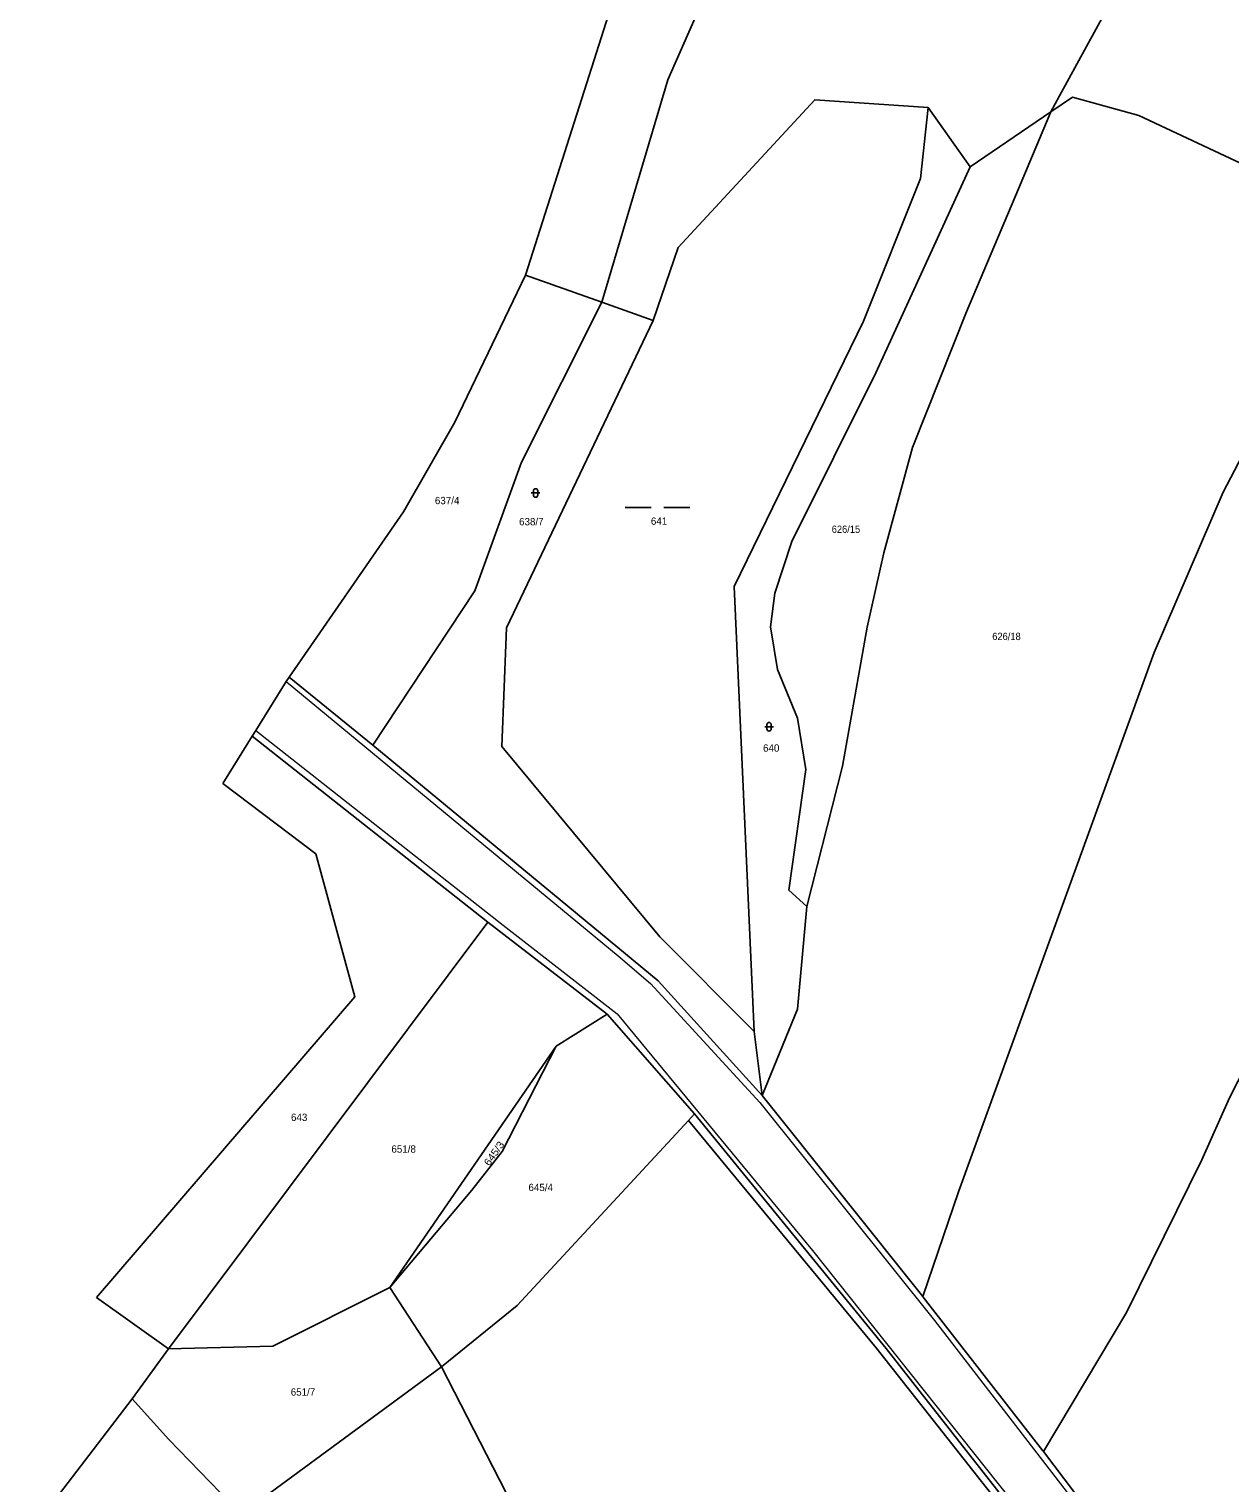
# Model space of a CAD drawing. Extents: x -687135 to -684370, y -1007309 to -1005782.
# Drawn here: x -685352.6 to -685073.8, y -1006317.9 to -1005980.6 of the extents above; entities that cross this region are included whole.
import ezdxf

# ---------------------------------------------------------------- set-up
doc = ezdxf.new("R2010")
doc.units = 0
doc.header["$LTSCALE"] = 0.68
for name, color, linetype, lineweight in [('1', 7, 'Continuous', 25), ('3', 7, 'Continuous', 25), ('4', 7, 'Continuous', 13)]:
    doc.layers.add(name, color=color, linetype=linetype, lineweight=lineweight)
doc.layers.add('2', color=7, linetype='Continuous')

msp = doc.modelspace()

# ---------------------------------------------------------------- linework, layer by layer
at = {"layer": '1'}
for p, q in [((-685218.37, -1006209.16), (-685230.23, -1006216.55)), ((-685230.23, -1006216.55), (-685268.8, -1006272.58)), ((-685198.1, -1006232.27), (-685199.53, -1006233.83)), ((-685268.8, -1006272.58), (-685256.82, -1006291)), ((-685256.82, -1006291), (-685303.33, -1006325.19))]:
    msp.add_line(p, q, dxfattribs=at)
for points in [[(-685201.33, -1005937.1), (-685215.2, -1005968.19), (-685237.31, -1006037.69)], [(-685186.26, -1005951.34), (-685204.26, -1005992.33), (-685219.65, -1006043.93), (-685207.69, -1006048.16)], [(-685115.38, -1005999.81), (-685113.34, -1005996.06), (-685094.6, -1005961.65)], [(-685207.69, -1006048.16), (-685201.93, -1006031.22), (-685170.17, -1005996.98), (-685143.84, -1005998.76)], [(-685043.78, -1006024.6), (-685094.94, -1006000.61), (-685110.34, -1005996.38), (-685115.38, -1005999.81)], [(-685143.84, -1005998.76), (-685145.67, -1006015.24), (-685158.9, -1006048.35), (-685188.9, -1006109.89), (-685184.28, -1006213.17), (-685182.43, -1006228.06)], [(-685172.02, -1006184.19), (-685163.73, -1006151.58), (-685158.05, -1006119.33), (-685154.12, -1006102.12), (-685147.52, -1006077.65), (-685134.94, -1006046.18), (-685122.85, -1006017.63), (-685115.38, -1005999.81)], [(-685143.84, -1005998.76), (-685134.13, -1006012.57), (-685115.38, -1005999.81)], [(-685172.02, -1006184.19), (-685176.18, -1006180.38), (-685172.25, -1006152.4), (-685174.22, -1006140.49), (-685178.84, -1006129.17), (-685180.47, -1006119.27), (-685179.43, -1006111.45), (-685175.49, -1006099.47), (-685156.01, -1006060.35), (-685134.13, -1006012.57)], [(-685145.13, -1006274.7), (-685136.85, -1006250.38), (-685091.37, -1006125.23), (-685075.37, -1006088.01), (-685067.37, -1006072.83), (-685050.82, -1006039.99), (-685046.05, -1006029.56), (-685043.78, -1006024.6)], [(-685272.75, -1006146.75), (-685249.08, -1006110.89), (-685238.29, -1006081.04), (-685219.65, -1006043.93), (-685237.31, -1006037.69), (-685253.78, -1006071.82)], [(-685207.69, -1006048.16), (-685241.72, -1006119.52), (-685242.87, -1006147.07), (-685206.16, -1006191.21), (-685184.28, -1006213.17)], [(-685117.08, -1006310.67), (-685097.85, -1006278.37), (-685080.32, -1006242.98), (-685073.88, -1006228.61), (-685048.94, -1006179.58), (-685036.71, -1006155.62), (-685020.67, -1006123.9), (-684995.04, -1006079.93), (-684987.31, -1006061.26), (-684983.8, -1006052.73)], [(-685253.78, -1006071.82), (-685265.69, -1006092.63), (-685292.24, -1006130.92)], [(-685292.24, -1006130.92), (-685292.91, -1006131.99), (-685299.95, -1006143.32), (-685300.78, -1006144.66)], [(-685182.43, -1006228.06), (-685206.53, -1006201.42), (-685229.32, -1006182.6), (-685272.75, -1006146.75), (-685292.24, -1006130.92)], [(-685336.92, -1006274.87), (-685320.22, -1006286.8), (-685246.05, -1006187.82), (-685300.78, -1006144.66), (-685307.57, -1006155.67)], [(-685307.57, -1006155.67), (-685286.01, -1006171.99), (-685276.95, -1006205.11), (-685293.09, -1006223.89), (-685336.92, -1006274.87)], [(-685182.43, -1006228.06), (-685174.22, -1006208), (-685172.02, -1006184.19)], [(-685246.05, -1006187.82), (-685218.37, -1006209.16), (-685198.1, -1006232.27)], [(-685268.8, -1006272.58), (-685249.83, -1006249.99), (-685242.79, -1006241.05), (-685230.23, -1006216.55)], [(-685117.08, -1006310.67), (-685117.2, -1006310.51), (-685145.04, -1006274.81), (-685145.13, -1006274.7), (-685182.43, -1006228.06)], [(-685256.82, -1006291), (-685239.28, -1006276.78), (-685199.53, -1006233.83)], [(-685199.53, -1006233.83), (-685155.92, -1006286.6), (-685117.05, -1006335.89), (-685095.12, -1006384.78), (-685075.56, -1006429.52)], [(-685061.94, -1006454.16), (-685073.28, -1006426.13), (-685089.64, -1006391.69), (-685115.59, -1006335.15), (-685153.62, -1006286.74), (-685198.1, -1006232.27)], [(-685268.8, -1006272.58), (-685296, -1006286.21), (-685320.22, -1006286.8), (-685321.45, -1006288.51), (-685328.64, -1006298.45)], [(-685175.13, -1006458.36), (-685198.89, -1006402.17), (-685211.49, -1006378.14), (-685237.4, -1006328.81), (-685256.82, -1006291)], [(-685303.33, -1006325.19), (-685320.13, -1006307.86), (-685328.64, -1006298.45), (-685352.59, -1006329.63)], [(-685091.4, -1006354.8), (-685102.68, -1006329.65), (-685117.08, -1006310.67)]]:
    msp.add_lwpolyline(points, dxfattribs=at)
at = {"layer": '3'}
for p, q in [((-685236.011, -1006088.221), (-685234.009, -1006088.221)), ((-685235.511, -1006087.721), (-685235.511, -1006088.722)), ((-685234.509, -1006088.722), (-685234.509, -1006087.721)), ((-685214.199, -1006091.6), (-685208.199, -1006091.6)), ((-685205.199, -1006091.6), (-685199.199, -1006091.6)), ((-685181.801, -1006142.451), (-685179.799, -1006142.451)), ((-685181.301, -1006141.951), (-685181.301, -1006142.952)), ((-685180.299, -1006142.952), (-685180.299, -1006141.951))]:
    msp.add_line(p, q, dxfattribs=at)
for centre, start, end in [((-685235.01, -1006087.7209), 0, 180), ((-685235.01, -1006088.7209), 180, 359.98789), ((-685180.8, -1006141.9509), 0, 180), ((-685180.8, -1006142.9509), 180, 359.98789)]:
    msp.add_arc(centre, 0.5, start, end, dxfattribs=at)
at = {"layer": '4'}
for p, q in [((-685292.91, -1006131.99), (-685215.86, -1006195.64)), ((-685299.95, -1006143.32), (-685242.51, -1006188.5)), ((-685170.68, -1006263.96), (-685114.29, -1006334.81))]:
    msp.add_line(p, q, dxfattribs=at)
for points in [[(-685242.51, -1006188.5), (-685216.07, -1006209.09), (-685170.68, -1006263.96)], [(-685215.86, -1006195.64), (-685208.32, -1006202.04), (-685182.9, -1006229.69), (-685142.36, -1006280.22), (-685104.01, -1006330), (-685085.82, -1006372.79)]]:
    msp.add_lwpolyline(points, dxfattribs=at)

# ---------------------------------------------------------------- texts
at = {"layer": '2'}
for s, p in [('637/4', (-685258.37, -1006090.82)), ('638/7', (-685238.83, -1006095.72)), ('641', (-685208.23, -1006095.6)), ('640', (-685182.19, -1006148.25)), ('643', (-685291.78, -1006233.94)), ('651/8', (-685268.47, -1006241.299)), ('645/4', (-685236.65, -1006250.21)), ('651/7', (-685291.84, -1006297.679))]:
    msp.add_text(s, height=1.7, dxfattribs=at).set_placement(p)
at = {"layer": '2', "width": 0.95}
for s, p in [('626/15', (-685166.25, -1006097.48)), ('626/18', (-685128.98, -1006122.35))]:
    msp.add_text(s, height=1.7, dxfattribs=at).set_placement(p)
at = {"layer": '2', "width": 1.1}
msp.add_text('645/3', height=1.7, rotation=55, dxfattribs=at).set_placement((-685245.743, -1006244.537))

doc.saveas('drawing.dxf')
